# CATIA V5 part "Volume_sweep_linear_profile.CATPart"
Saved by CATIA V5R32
Part number: Part1
Bounding box of the stored display mesh (mm): x -63.725 to 63.725, y -58.359 to 47.359, z -20 to 20
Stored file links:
  D:\PROJECTS\Project 2022\CATIA V5 6R 2022\Resources\Part Files\c17_catia_v6_6r2022_prt\Volume_sweep_linear_profile.CATPart
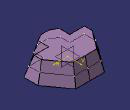
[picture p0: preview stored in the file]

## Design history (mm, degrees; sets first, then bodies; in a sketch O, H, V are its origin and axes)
Set1
  Sketch1 on xy-plane, origin (0, 0, 0), H (1, 0, 0), V (0, 1, 0)
    point P1 (0, 42)
    line L1 (0, 42) -> (-27.5, 42)
    point P2 (-27.5, 42)
    line L2 (-27.5, 42) -> (-58.3665, 0)
    point P3 (-58.3665, 0)
    line L3 (-58.3665, 0) -> (-58.3665, -23)
    point P4 (-58.3665, -23)
    line L4 (-58.3665, -23) -> (-27.5, -23)
    point P5 (-27.5, -23)
    line L5 (-27.5, -23) -> (-27.5, -42.8964)
    point P6 (-27.5, -42.8964)
    line L6 (-27.5, -42.8964) -> (-10, -53)
    point P7 (-10, -53)
    line L7 (-10, -53) -> (0, -53)
    point P8 (0, -53)
    reference intersected line E1 through (0, 0) direction (0, 1) from yz-plane
    point P11 (0, 0)
    construction line L8 through (0, 0) direction (0, 1)
    point P12 (0, 42)
    point P13 (27.5, 42)
    point P14 (58.3665, 0)
    point P15 (58.3665, -23)
    point P16 (27.5, -23)
    point P17 (27.5, -42.8964)
    point P18 (10, -53)
    point P19 (0, -53)
    line L9 (0, 42) -> (27.5, 42)
    line L10 (27.5, 42) -> (58.3665, 0)
    line L11 (58.3665, 0) -> (58.3665, -23)
    line L12 (58.3665, -23) -> (27.5, -23)
    line L13 (27.5, -23) -> (27.5, -42.8964)
    line L14 (27.5, -42.8964) -> (10, -53)
    line L15 (10, -53) -> (0, -53)
    distance P14 P13 V = 42
    distance P13 P2 = 55
    distance P15 P14 = 23
    distance L11 L8 = 58.3665
    angle L14 L15 = 30
    distance P18 P7 = 20
    distance P17 P6 = 55
    distance L9 L15 = 95
    coincidence: P1 V, P3 H, P8 V, P7 L15, P8 L15, P18 L7, P19 L7
    horizontal: L1 H, L4 H, L7 H, L15 H
    vertical: L3 V, L5 V
    symmetry: O P11 E1, V L8 E1, P1 P12 E1, P2 P13 E1, P3 P14 E1, P4 P15 E1, P5 P16 E1, P6 P17 E1, P7 P18 E1, P8 P19 E1, L1 L9 E1, L2 L10 E1, L3 L11 E1, L4 L12 E1, L5 L13 E1, L6 L14 E1, L7 L15 E1
  Sweep1: type Segment, GuideCrv Sketch1, Length1 20, Length2 20, Angle 15, DraftDirection xy-plane
Body1 (main body)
